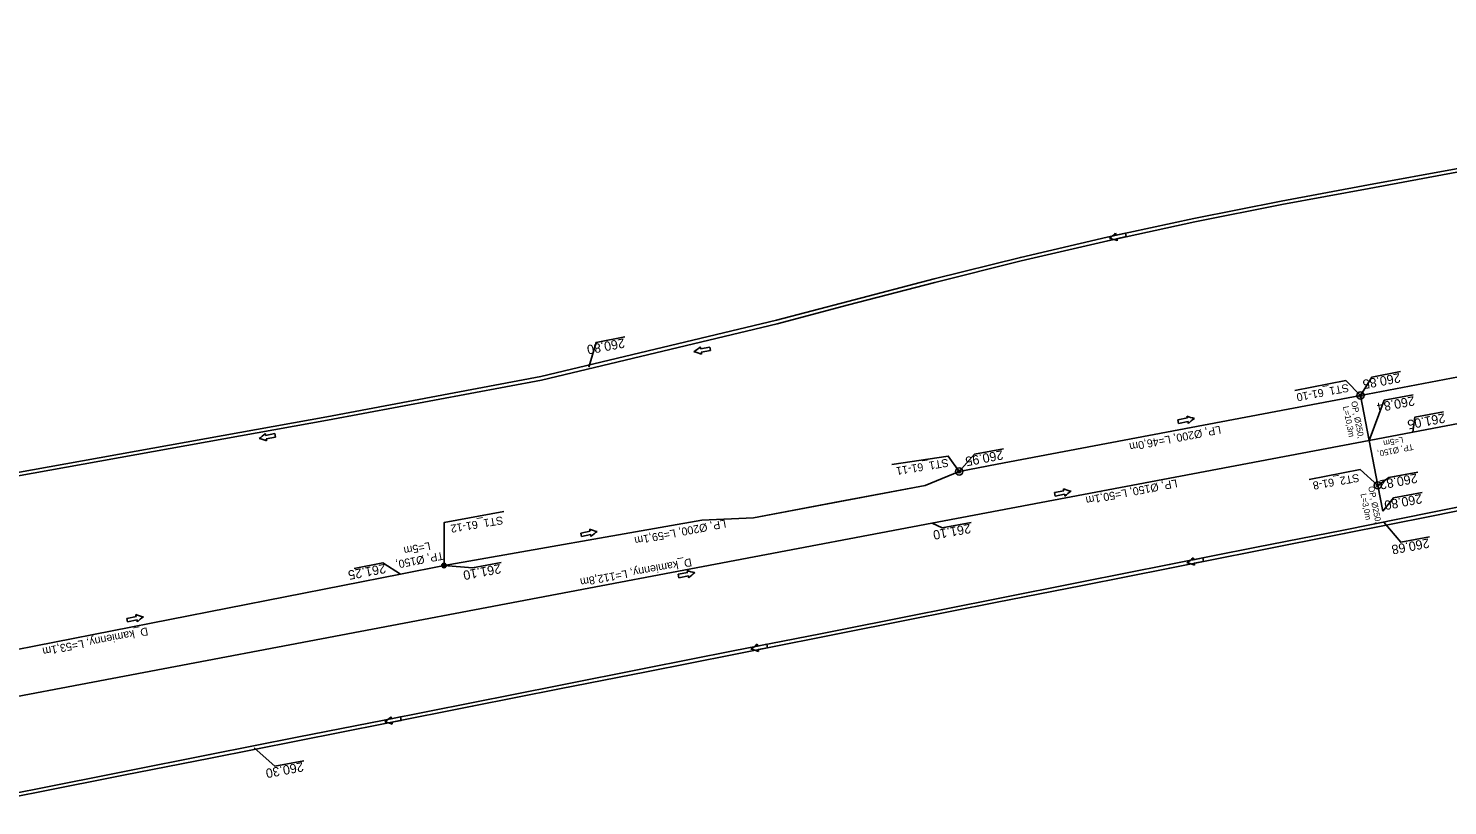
# Model space of a CAD drawing. Extents: x -1 to 65640748, y -22 to 5530284.
# Drawn here: x 6557234.6 to 6557394.3, y 5528623.3 to 5528710.8 of the extents above; entities that cross this region are included whole.
import ezdxf

# ---------------------------------------------------------------- set-up
doc = ezdxf.new("R2010")
doc.units = 0
for name, color, linetype in [('TOR_PROF-studnie i osadniki', 7, 'Continuous'), ('TOR_PS_ODW-drenaze', 7, 'Continuous'), ('TOR_PS_ODW-drenokolektory', 7, 'Continuous'), ('TOR_PS_ODW-kolektory', 7, 'Continuous'), ('TOR_PS_ODW-studnie PEHD', 7, 'Continuous'), ('TOR_PS_OPIS_O-opisy rurociagow', 7, 'Continuous'), ('TOR_PS_OPIS_O-opisy studni', 7, 'Continuous'), ('TOR_PS_OPIS_T-INFO', 7, 'Continuous'), ('TOR_PS_T-rowy otwarte umocnione', 7, 'Continuous')]:
    doc.layers.add(name, color=color, linetype=linetype)

msp = doc.modelspace()

# ---------------------------------------------------------------- linework, layer by layer
at = {"layer": 'TOR_PROF-studnie i osadniki'}
for radius in [0.25, 0.125]:
    msp.add_circle((6557281.38, 5528650.34), radius, dxfattribs=at)
at = {"layer": 'TOR_PS_ODW-drenaze'}
for p, q in [((6557390.35, 5528665.35), (6557430.18, 5528672.9)), ((6557281.38, 5528650.34), (6557276.47, 5528649.38)), ((6557276.47, 5528649.38), (6557224.41, 5528639.14))]:
    msp.add_line(p, q, dxfattribs=at)
for points in [[(6557385.44, 5528664.42), (6557336.26, 5528655.1)], [(6557385.44, 5528664.42), (6557336.26, 5528655.1)], [(6557385.44, 5528664.42), (6557336.26, 5528655.1)], [(6557390.35, 5528665.35), (6557385.44, 5528664.42)], [(6557390.35, 5528665.35), (6557385.44, 5528664.42)], [(6557390.35, 5528665.35), (6557385.44, 5528664.42)], [(6557336.26, 5528655.1), (6557225.43, 5528634.09)]]:
    msp.add_lwpolyline(points, dxfattribs=at)
at = {"layer": 'TOR_PS_ODW-drenokolektory'}
for points in [[(6557443.42, 5528680.65), (6557410.59, 5528674.43), (6557408.68, 5528675.09), (6557403.31, 5528674.06), (6557401.81, 5528672.76), (6557384.47, 5528669.48)], [(6557384.47, 5528669.48), (6557343.6, 5528661.73), (6557339.33, 5528660.92), (6557339.33, 5528660.92)], [(6557384.47, 5528669.48), (6557343.6, 5528661.73), (6557339.33, 5528660.92)], [(6557339.33, 5528660.92), (6557335.5, 5528659.34), (6557316.2, 5528655.72), (6557310.38, 5528655.46), (6557281.38, 5528650.34)], [(6557339.33, 5528660.92), (6557335.5, 5528659.34), (6557325.85, 5528657.53), (6557316.2, 5528655.72), (6557310.38, 5528655.46), (6557281.38, 5528650.34)], [(6557339.33, 5528660.92), (6557335.5, 5528659.34), (6557316.2, 5528655.72), (6557310.38, 5528655.46), (6557281.38, 5528650.34)]]:
    msp.add_lwpolyline(points, dxfattribs=at)
at = {"layer": 'TOR_PS_ODW-kolektory'}
for p, q in [((6557386.41, 5528659.36), (6557384.47, 5528669.48)), ((6557386.97, 5528656.44), (6557386.41, 5528659.36))]:
    msp.add_line(p, q, dxfattribs=at)
at = {"layer": 'TOR_PS_ODW-studnie PEHD'}
for centre, radius in [((6557384.47, 5528669.48), 0.4), ((6557384.47, 5528669.48), 0.145), ((6557339.33, 5528660.92), 0.4), ((6557339.33, 5528660.92), 0.145), ((6557386.41, 5528659.36), 0.4), ((6557386.41, 5528659.36), 0.145), ((6557281.38, 5528650.34), 0.25), ((6557281.38, 5528650.34), 0.112)]:
    msp.add_circle(centre, radius, dxfattribs=at)
at = {"layer": 'TOR_PS_OPIS_O-opisy rurociagow'}
for p, q in [((6557358.02, 5528687.75), (6557356.95, 5528687.52)), ((6557356.95, 5528687.52), (6557358.02, 5528687.75)), ((6557357.04, 5528687.13), (6557358.11, 5528687.36)), ((6557357.04, 5528687.13), (6557358.11, 5528687.36)), ((6557358.11, 5528687.36), (6557358.02, 5528687.75)), ((6557358.11, 5528687.36), (6557358.02, 5528687.75)), ((6557311.29, 5528674.93), (6557310.21, 5528674.74)), ((6557310.21, 5528674.74), (6557311.29, 5528674.93)), ((6557310.29, 5528674.34), (6557311.36, 5528674.54)), ((6557310.29, 5528674.34), (6557311.36, 5528674.54)), ((6557311.36, 5528674.54), (6557311.29, 5528674.93)), ((6557311.36, 5528674.54), (6557311.29, 5528674.93)), ((6557363.93, 5528666.73), (6557365, 5528666.95)), ((6557365, 5528666.95), (6557363.93, 5528666.73)), ((6557364.01, 5528666.33), (6557363.93, 5528666.73)), ((6557364.01, 5528666.33), (6557363.93, 5528666.73)), ((6557365.08, 5528666.55), (6557364.01, 5528666.33)), ((6557365.08, 5528666.55), (6557364.01, 5528666.33)), ((6557262.36, 5528665.19), (6557261.29, 5528664.98)), ((6557261.29, 5528664.98), (6557262.36, 5528665.19)), ((6557261.37, 5528664.59), (6557262.44, 5528664.8)), ((6557261.37, 5528664.59), (6557262.44, 5528664.8)), ((6557262.44, 5528664.8), (6557262.36, 5528665.19)), ((6557262.44, 5528664.8), (6557262.36, 5528665.19)), ((6557350.04, 5528658.54), (6557351.11, 5528658.76)), ((6557351.11, 5528658.76), (6557350.04, 5528658.54)), ((6557350.12, 5528658.15), (6557350.04, 5528658.54)), ((6557350.12, 5528658.15), (6557350.04, 5528658.54)), ((6557351.19, 5528658.37), (6557350.12, 5528658.15)), ((6557351.19, 5528658.37), (6557350.12, 5528658.15)), ((6557296.75, 5528653.99), (6557297.82, 5528654.21)), ((6557297.82, 5528654.21), (6557296.75, 5528653.99)), ((6557296.83, 5528653.6), (6557296.75, 5528653.99)), ((6557296.83, 5528653.6), (6557296.75, 5528653.99)), ((6557297.9, 5528653.82), (6557296.83, 5528653.6)), ((6557297.9, 5528653.82), (6557296.83, 5528653.6)), ((6557366.74, 5528651.19), (6557365.67, 5528650.98)), ((6557365.67, 5528650.98), (6557366.74, 5528651.19)), ((6557366.82, 5528650.8), (6557366.74, 5528651.19)), ((6557366.82, 5528650.8), (6557366.74, 5528651.19)), ((6557307.73, 5528649.35), (6557308.8, 5528649.57)), ((6557308.8, 5528649.57), (6557307.73, 5528649.35)), ((6557365.75, 5528650.59), (6557366.82, 5528650.8)), ((6557365.75, 5528650.59), (6557366.82, 5528650.8)), ((6557307.81, 5528648.96), (6557307.73, 5528649.35)), ((6557307.81, 5528648.96), (6557307.73, 5528649.35)), ((6557308.88, 5528649.18), (6557307.81, 5528648.96)), ((6557308.88, 5528649.18), (6557307.81, 5528648.96)), ((6557245.7, 5528644.39), (6557246.77, 5528644.61)), ((6557246.77, 5528644.61), (6557245.7, 5528644.39)), ((6557245.78, 5528643.99), (6557245.7, 5528644.39)), ((6557245.78, 5528643.99), (6557245.7, 5528644.39)), ((6557246.85, 5528644.21), (6557245.78, 5528643.99)), ((6557246.85, 5528644.21), (6557245.78, 5528643.99)), ((6557317.7, 5528641.47), (6557316.63, 5528641.26)), ((6557316.63, 5528641.26), (6557317.7, 5528641.47)), ((6557316.7, 5528640.87), (6557317.77, 5528641.08)), ((6557316.7, 5528640.87), (6557317.77, 5528641.08)), ((6557317.77, 5528641.08), (6557317.7, 5528641.47)), ((6557317.77, 5528641.08), (6557317.7, 5528641.47)), ((6557276.49, 5528633.3), (6557275.42, 5528633.09)), ((6557275.42, 5528633.09), (6557276.49, 5528633.3)), ((6557275.5, 5528632.7), (6557276.57, 5528632.91)), ((6557275.5, 5528632.7), (6557276.57, 5528632.91)), ((6557276.57, 5528632.91), (6557276.49, 5528633.3)), ((6557276.57, 5528632.91), (6557276.49, 5528633.3))]:
    msp.add_line(p, q, dxfattribs=at)
for points in [[(6557356.92, 5528687.74), (6557356.92, 5528687.74)], [(6557357.1, 5528686.91), (6557357.1, 5528686.91)], [(6557310.18, 5528674.96), (6557310.18, 5528674.96)], [(6557310.34, 5528674.13), (6557310.34, 5528674.13)], [(6557364.94, 5528667.16), (6557364.94, 5528667.16)], [(6557365.12, 5528666.33), (6557365.12, 5528666.33)], [(6557261.26, 5528665.2), (6557261.26, 5528665.2)], [(6557261.42, 5528664.37), (6557261.42, 5528664.37)], [(6557351.06, 5528658.98), (6557351.06, 5528658.98)], [(6557351.23, 5528658.14), (6557351.23, 5528658.14)], [(6557297.76, 5528654.43), (6557297.76, 5528654.43)], [(6557297.93, 5528653.6), (6557297.93, 5528653.6)], [(6557365.64, 5528651.2), (6557365.64, 5528651.2)], [(6557308.74, 5528649.79), (6557308.74, 5528649.79)], [(6557365.8, 5528650.37), (6557365.8, 5528650.37)], [(6557308.91, 5528648.96), (6557308.91, 5528648.96)], [(6557246.71, 5528644.82), (6557246.71, 5528644.82)], [(6557246.88, 5528643.99), (6557246.88, 5528643.99)], [(6557316.59, 5528641.48), (6557316.59, 5528641.48)], [(6557316.76, 5528640.65), (6557316.76, 5528640.65)], [(6557275.39, 5528633.31), (6557275.39, 5528633.31)], [(6557275.55, 5528632.48), (6557275.55, 5528632.48)]]:
    msp.add_lwpolyline(points, dxfattribs=at)
for centre, radius, start, end in [((6557353.38, 5528691.16), 4.92, 305.5344, 315.9162), ((6557353.38, 5528691.16), 4.92, 305.5344, 315.9162), ((6557355.29, 5528682.33), 4.92, 68.4965, 78.8783), ((6557355.29, 5528682.33), 4.92, 68.4965, 78.8783), ((6557356.5, 5528687.56), 0.458, 355.3404, 23.8017), ((6557356.5, 5528687.56), 0.458, 355.3404, 23.8017), ((6557356.64, 5528686.9), 0.458, 0.6111, 29.0723), ((6557356.64, 5528686.9), 0.458, 0.6111, 29.0723), ((6557306.77, 5528678.5), 4.92, 303.6098, 313.9917), ((6557306.77, 5528678.5), 4.92, 303.6098, 313.9917), ((6557308.38, 5528669.61), 4.92, 66.5719, 76.9538), ((6557308.38, 5528669.61), 4.92, 66.5719, 76.9538), ((6557309.76, 5528674.79), 0.458, 353.4158, 21.8771), ((6557309.76, 5528674.79), 0.458, 353.4158, 21.8771), ((6557309.88, 5528674.14), 0.458, 358.6865, 27.1477), ((6557309.88, 5528674.14), 0.458, 358.6865, 27.1477), ((6557365.4, 5528667.16), 0.458, 180.0164, 208.4776), ((6557366.79, 5528671.72), 4.92, 247.9018, 258.2836), ((6557366.79, 5528671.72), 4.92, 247.9018, 258.2836), ((6557365.4, 5528667.16), 0.458, 180.0164, 208.4776), ((6557365.54, 5528666.51), 0.458, 174.7457, 203.207), ((6557365.54, 5528666.51), 0.458, 174.7457, 203.207), ((6557368.61, 5528662.87), 4.92, 124.9397, 135.3215), ((6557368.61, 5528662.87), 4.92, 124.9397, 135.3215), ((6557257.79, 5528668.69), 4.92, 304.4436, 314.8254), ((6557257.79, 5528668.69), 4.92, 304.4436, 314.8254), ((6557259.53, 5528659.83), 4.92, 67.4057, 77.7875), ((6557259.53, 5528659.83), 4.92, 67.4057, 77.7875), ((6557260.83, 5528665.02), 0.458, 354.2496, 22.7109), ((6557260.83, 5528665.02), 0.458, 354.2496, 22.7109), ((6557260.96, 5528664.37), 0.458, 359.5203, 27.9815), ((6557260.96, 5528664.37), 0.458, 359.5203, 27.9815), ((6557351.51, 5528658.98), 0.458, 180.0164, 208.4776), ((6557352.91, 5528663.53), 4.92, 247.9018, 258.2836), ((6557352.91, 5528663.53), 4.92, 247.9018, 258.2836), ((6557351.51, 5528658.98), 0.458, 180.0164, 208.4776), ((6557351.65, 5528658.32), 0.458, 174.7457, 203.207), ((6557351.65, 5528658.32), 0.458, 174.7457, 203.207), ((6557354.72, 5528654.69), 4.92, 124.9397, 135.3215), ((6557354.72, 5528654.69), 4.92, 124.9397, 135.3215), ((6557298.22, 5528654.43), 0.458, 180.0164, 208.4776), ((6557299.61, 5528658.99), 4.92, 247.9018, 258.2836), ((6557299.61, 5528658.99), 4.92, 247.9018, 258.2836), ((6557298.22, 5528654.43), 0.458, 180.0164, 208.4776), ((6557298.36, 5528653.78), 0.458, 174.7457, 203.207), ((6557298.36, 5528653.78), 0.458, 174.7457, 203.207), ((6557301.43, 5528650.14), 4.92, 124.9397, 135.3215), ((6557301.43, 5528650.14), 4.92, 124.9397, 135.3215), ((6557362.16, 5528654.69), 4.92, 304.5425, 314.9243), ((6557362.16, 5528654.69), 4.92, 304.5425, 314.9243), ((6557365.22, 5528651.03), 0.458, 354.3485, 22.8097), ((6557365.22, 5528651.03), 0.458, 354.3485, 22.8097), ((6557309.2, 5528649.79), 0.458, 180.0164, 208.4776), ((6557310.59, 5528654.35), 4.92, 247.9018, 258.2836), ((6557310.59, 5528654.35), 4.92, 247.9018, 258.2836), ((6557309.2, 5528649.79), 0.458, 180.0164, 208.4776), ((6557312.41, 5528645.5), 4.92, 124.9397, 135.3215), ((6557312.41, 5528645.5), 4.92, 124.9397, 135.3215), ((6557363.92, 5528645.83), 4.92, 67.5046, 77.8864), ((6557363.92, 5528645.83), 4.92, 67.5046, 77.8864), ((6557365.34, 5528650.37), 0.458, 359.6191, 28.0804), ((6557365.34, 5528650.37), 0.458, 359.6191, 28.0804), ((6557309.33, 5528649.14), 0.458, 174.7457, 203.207), ((6557309.33, 5528649.14), 0.458, 174.7457, 203.207), ((6557247.17, 5528644.82), 0.458, 180.0164, 208.4776), ((6557248.56, 5528649.38), 4.92, 247.9018, 258.2836), ((6557248.56, 5528649.38), 4.92, 247.9018, 258.2836), ((6557247.17, 5528644.82), 0.458, 180.0164, 208.4776), ((6557247.3, 5528644.17), 0.458, 174.7457, 203.207), ((6557247.3, 5528644.17), 0.458, 174.7457, 203.207), ((6557250.38, 5528640.53), 4.92, 124.9397, 135.3215), ((6557250.38, 5528640.53), 4.92, 124.9397, 135.3215), ((6557313.12, 5528644.96), 4.92, 304.538, 314.9198), ((6557313.12, 5528644.96), 4.92, 304.538, 314.9198), ((6557314.87, 5528636.11), 4.92, 67.5001, 77.8819), ((6557314.87, 5528636.11), 4.92, 67.5001, 77.8819), ((6557316.17, 5528641.3), 0.458, 354.344, 22.8052), ((6557316.17, 5528641.3), 0.458, 354.344, 22.8052), ((6557316.3, 5528640.65), 0.458, 359.6146, 28.0759), ((6557316.3, 5528640.65), 0.458, 359.6146, 28.0759), ((6557271.92, 5528636.8), 4.92, 304.5425, 314.9243), ((6557271.92, 5528636.8), 4.92, 304.5425, 314.9243), ((6557273.67, 5528627.94), 4.92, 67.5046, 77.8864), ((6557273.67, 5528627.94), 4.92, 67.5046, 77.8864), ((6557274.97, 5528633.14), 0.458, 354.3485, 22.8097), ((6557274.97, 5528633.14), 0.458, 354.3485, 22.8097), ((6557275.1, 5528632.48), 0.458, 359.6191, 28.0804), ((6557275.1, 5528632.48), 0.458, 359.6191, 28.0804)]:
    msp.add_arc(centre, radius, start, end, dxfattribs=at)
at = {"layer": 'TOR_PS_OPIS_T-INFO'}
for points in [[(6557297.67, 5528672.68), (6557298.49, 5528675.46), (6557301.73, 5528676.07)], [(6557384.47, 5528669.48), (6557385.75, 5528671.55), (6557388.98, 5528672.16)], [(6557384.47, 5528669.48), (6557382.82, 5528671.15), (6557377.08, 5528670.04)], [(6557385.44, 5528664.42), (6557387.14, 5528668.95), (6557390.38, 5528669.55)], [(6557390.35, 5528665.35), (6557390.57, 5528667.02), (6557393.81, 5528667.63)], [(6557339.33, 5528660.92), (6557338.1, 5528662.66), (6557331.76, 5528661.7)], [(6557339.33, 5528660.92), (6557341.06, 5528662.88), (6557344.3, 5528663.48)], [(6557386.41, 5528659.36), (6557384.43, 5528661.13), (6557378.69, 5528660.02)], [(6557386.41, 5528659.36), (6557387.67, 5528660.25), (6557390.9, 5528660.86)], [(6557386.97, 5528656.44), (6557388.18, 5528657.95), (6557391.42, 5528658.55)], [(6557281.38, 5528650.34), (6557281.38, 5528655.18), (6557288.09, 5528656.43)], [(6557336.3, 5528655.11), (6557337.42, 5528654.59), (6557340.66, 5528655.19)], [(6557387.11, 5528655.22), (6557389, 5528652.95), (6557392.24, 5528653.55)], [(6557276.47, 5528649.38), (6557274.5, 5528650.63), (6557271.27, 5528650)], [(6557281.38, 5528650.34), (6557284.57, 5528650.06), (6557287.81, 5528650.67)], [(6557260.01, 5528629.83), (6557262.36, 5528627.76), (6557265.6, 5528628.36)]]:
    msp.add_lwpolyline(points, dxfattribs=at)
at = {"layer": 'TOR_PS_T-rowy otwarte umocnione'}
for points in [[(6557465.69, 5528710.8), (6557444.16, 5528705.25), (6557442.23, 5528704.73), (6557434.38, 5528703.18), (6557429.47, 5528702.21), (6557424.59, 5528701.13), (6557414.82, 5528698.97), (6557409.94, 5528697.89), (6557405.03, 5528696.92), (6557395.22, 5528694.99), (6557385.38, 5528693.18), (6557375.55, 5528691.36), (6557365.74, 5528689.4), (6557355.96, 5528687.29), (6557346.22, 5528685.02), (6557336.5, 5528682.6), (6557326.8, 5528680.06), (6557318.78, 5528677.95)], [(6557465.77, 5528710.41), (6557442.3, 5528704.33), (6557434.45, 5528702.79), (6557429.55, 5528701.82), (6557424.66, 5528700.74), (6557414.89, 5528698.58), (6557410.01, 5528697.49), (6557405.1, 5528696.53), (6557395.29, 5528694.6), (6557385.46, 5528692.78), (6557375.62, 5528690.97), (6557365.82, 5528689.01), (6557356.04, 5528686.9), (6557346.29, 5528684.63), (6557336.57, 5528682.21), (6557326.88, 5528679.67), (6557318.86, 5528677.55)], [(6557318.78, 5528677.95), (6557292.28, 5528671.62), (6557268.19, 5528667.08), (6557229.02, 5528660.02)], [(6557318.86, 5528677.55), (6557292.35, 5528671.22), (6557268.27, 5528666.69), (6557229.1, 5528659.63)], [(6557463.97, 5528669.8), (6557463.9, 5528670.2), (6557451.29, 5528667.66), (6557449.33, 5528667.27), (6557441.48, 5528665.69), (6557436.58, 5528664.71), (6557431.66, 5528663.83), (6557421.81, 5528662.09), (6557416.89, 5528661.22), (6557411.98, 5528660.23), (6557402.18, 5528658.26), (6557392.38, 5528656.29), (6557382.57, 5528654.33), (6557372.76, 5528652.39), (6557362.95, 5528650.44), (6557353.14, 5528648.5), (6557343.33, 5528646.55), (6557333.52, 5528644.61), (6557325.41, 5528643)], [(6557402.25, 5528657.87), (6557392.45, 5528655.9), (6557382.64, 5528653.94), (6557372.83, 5528651.99), (6557363.02, 5528650.05), (6557353.21, 5528648.1), (6557343.41, 5528646.16), (6557333.6, 5528644.22), (6557325.48, 5528642.61), (6557325.48, 5528642.61), (6557323.79, 5528642.27), (6557313.98, 5528640.33), (6557304.17, 5528638.38), (6557294.36, 5528636.44), (6557284.55, 5528634.49), (6557274.74, 5528632.55)], [(6557325.41, 5528643), (6557323.71, 5528642.66), (6557313.9, 5528640.72), (6557304.09, 5528638.78), (6557294.28, 5528636.83), (6557284.47, 5528634.89), (6557274.66, 5528632.94)], [(6557274.66, 5528632.94), (6557264.86, 5528631), (6557255.05, 5528629.05), (6557245.24, 5528627.11), (6557235.64, 5528625.21)], [(6557274.66, 5528632.94), (6557264.86, 5528631), (6557255.05, 5528629.05), (6557245.24, 5528627.11), (6557235.64, 5528625.21)], [(6557274.74, 5528632.55), (6557264.93, 5528630.6), (6557255.12, 5528628.66), (6557245.31, 5528626.72), (6557235.72, 5528624.82)], [(6557274.74, 5528632.55), (6557264.93, 5528630.6), (6557255.12, 5528628.66), (6557245.31, 5528626.72), (6557235.72, 5528624.82)], [(6557235.64, 5528625.21), (6557227.96, 5528623.7)], [(6557235.72, 5528624.82), (6557228.05, 5528623.31), (6557227.96, 5528623.7)]]:
    msp.add_lwpolyline(points, dxfattribs=at)

# ---------------------------------------------------------------- texts
at = {"layer": 'TOR_PS_OPIS_O-opisy rurociagow'}
for s, height, rotation, p in [('OP, Ø250, ', 0.675, 281.0373, (6557383.41, 5528668.78)), ('L=10,3m', 0.675, 281.0373, (6557382.49, 5528668.22)), ('LP, Ø200, L=46,0m', 0.9, 190.9157, (6557368.68, 5528666.08)), ('TP, Ø150, ', 0.675, 191.303, (6557390.35, 5528664.03)), ('L=5m', 0.675, 191.303, (6557389.22, 5528664.84)), ('LP, Ø150, L=50,1m', 0.9, 190.9157, (6557363.77, 5528660.05)), ('OP, Ø250, ', 0.675, 281.3217, (6557385.33, 5528659.2)), ('L=3,0m', 0.675, 281.3217, (6557384.46, 5528658.38)), ('LP, Ø200, L=59,1m', 0.9, 190.9157, (6557313.01, 5528655.52)), ('L=5m', 0.9, 190.9157, (6557279.76, 5528652.99)), ('TP, Ø150, ', 0.9, 190.9157, (6557281.25, 5528651.9)), ('D_kamienny, L=112,8m', 0.9, 190.3457, (6557309.16, 5528651.16)), ('D_kamienny, L=53,1m', 0.9, 191.128, (6557247.99, 5528643.39))]:
    msp.add_text(s, height=height, rotation=rotation, dxfattribs=at).set_placement(p)
at = {"layer": 'TOR_PS_OPIS_O-opisy studni'}
for s, rotation, p in [('ST1_61-10', 190.823, (6557383.06, 5528670.8)), ('ST1_61-11', 189.4791, (6557338.05, 5528662.37)), ('ST2_61-8', 190.0258, (6557384.25, 5528660.67)), ('ST1_61-12', 189.5633, (6557287.94, 5528655.89))]:
    msp.add_text(s, height=0.9, rotation=rotation, dxfattribs=at).set_placement(p)
at = {"layer": 'TOR_PS_OPIS_T-INFO'}
for s, rotation, p in [('260.80', 190.7506, (6557301.6, 5528675.92)), ('260.85', 190.7506, (6557388.86, 5528672.01)), ('260.84', 190.7506, (6557390.46, 5528669.41)), ('261.05', 190.7506, (6557393.89, 5528667.48)), ('260.95', 190.7506, (6557344.17, 5528663.33)), ('260.82', 190.7506, (6557390.77, 5528660.71)), ('260.80', 190.7506, (6557391.29, 5528658.4)), ('261.10', 190.7506, (6557340.53, 5528655.05)), ('260.68', 190.7506, (6557392.11, 5528653.4)), ('261.25', 190.7159, (6557274.73, 5528650.54)), ('261.10', 190.7506, (6557287.68, 5528650.52)), ('260.30', 190.7506, (6557265.47, 5528628.22))]:
    msp.add_text(s, height=1.05, rotation=rotation, dxfattribs=at).set_placement(p)

doc.saveas('drawing.dxf')
